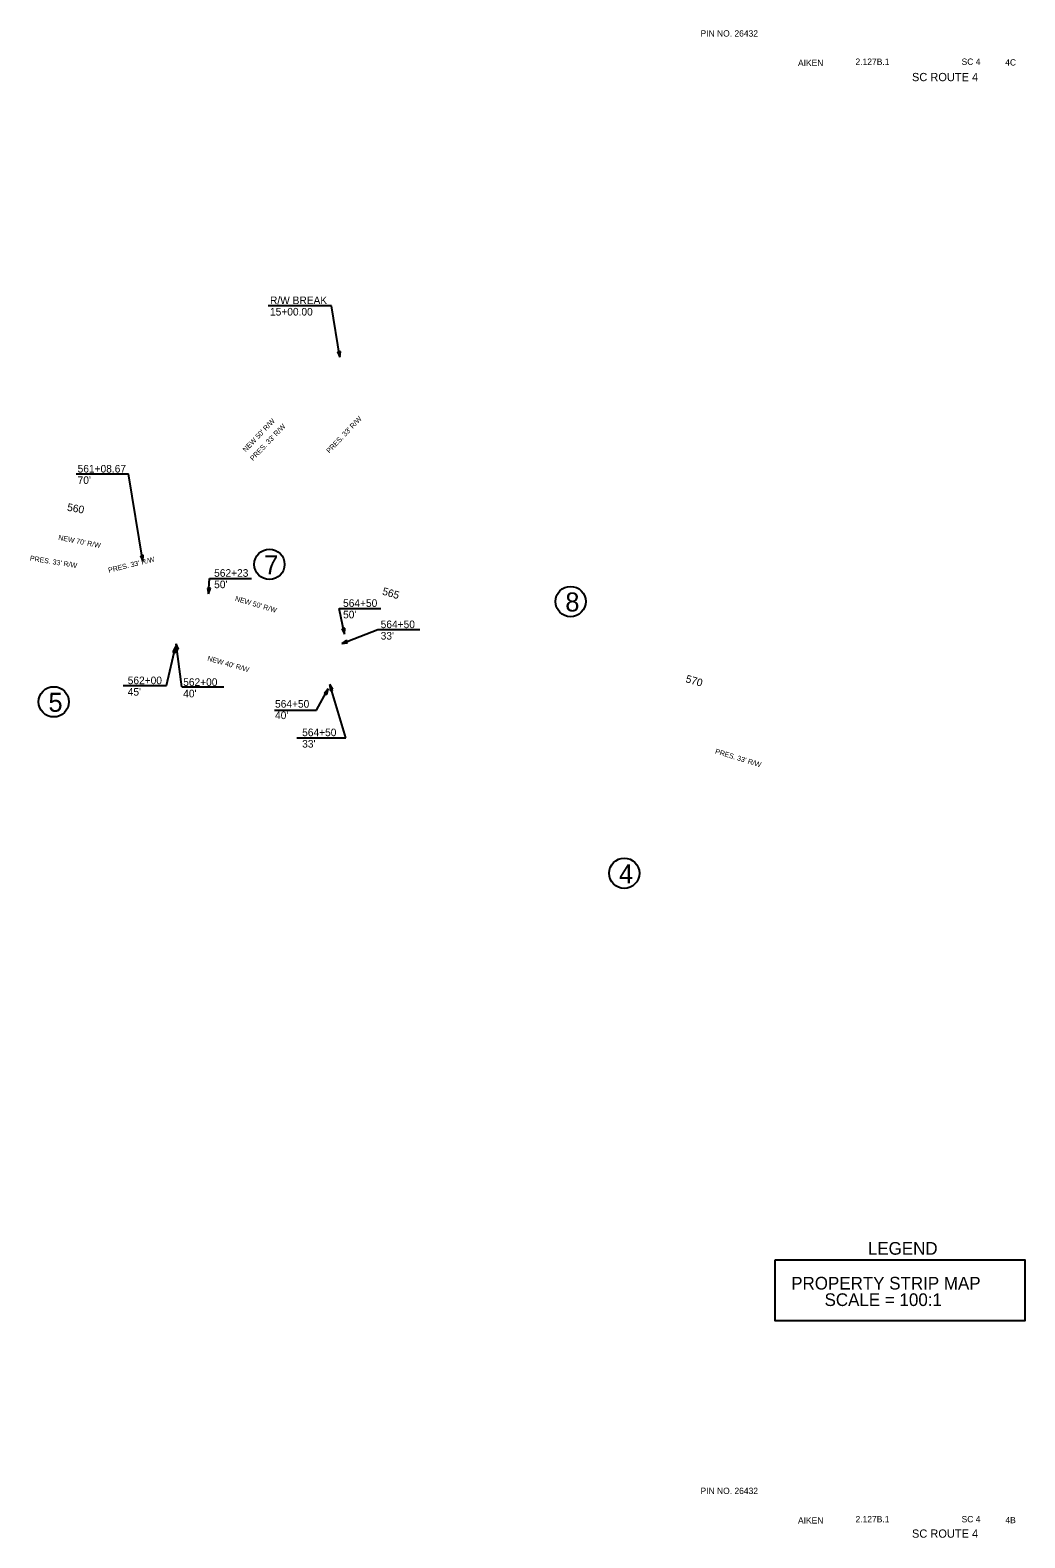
# Model space of a CAD drawing. Extents: x -64038 to -60878, y 1838 to 8465.
# Drawn here: x -62447 to -60878, y 6087 to 8465 of the extents above; entities that cross this region are included whole.
import ezdxf

# ---------------------------------------------------------------- set-up
doc = ezdxf.new("R2010")
doc.units = 0
for name, color, linetype in [('Level 1', 7, 'Continuous'), ('Level 13', 7, 'Continuous'), ('Level 21', 7, 'Continuous'), ('Level 24', 7, 'Continuous'), ('Level 25', 7, 'Continuous'), ('Level 33', 7, 'Continuous')]:
    doc.layers.add(name, color=color, linetype=linetype)

msp = doc.modelspace()

# ---------------------------------------------------------------- linework, layer by layer
at = {"layer": 'Level 1'}
msp.add_lwpolyline([(-61272.3, 6525.3), (-60878.4, 6525.3), (-60878.4, 6429), (-61272.3, 6429)], close=True, dxfattribs=at)
at = {"layer": 'Level 24'}
for p, q in [((-61957.9, 7958.1), (-61962.4, 7957.4)), ((-61962.4, 7957.4), (-61958.7, 7948.9)), ((-61958.7, 7948.9), (-61957.9, 7958.1)), ((-62268.7, 7636.6), (-62273.1, 7635.8)), ((-62273.1, 7635.8), (-62269.4, 7627.3)), ((-62269.4, 7627.3), (-62268.7, 7636.6)), ((-62162.8, 7584.6), (-62167.3, 7584.9)), ((-62167.3, 7584.9), (-62165.8, 7575.8)), ((-62165.8, 7575.8), (-62162.8, 7584.6)), ((-61951, 7521.5), (-61955.4, 7520.6)), ((-61955.4, 7520.6), (-61951.4, 7512.3)), ((-61951.4, 7512.3), (-61951, 7521.5)), ((-62218.1, 7492.2), (-62222.3, 7484)), ((-62217.9, 7482.9), (-62218.1, 7492.2)), ((-62216.7, 7497), (-62217.7, 7487.8)), ((-62213.3, 7488.4), (-62216.7, 7497)), ((-61948.2, 7502.9), (-61955.8, 7497.6)), ((-61948.2, 7502.9), (-61955.8, 7497.6)), ((-61955.8, 7497.6), (-61946.6, 7498.7)), ((-61955.8, 7497.6), (-61946.6, 7498.7)), ((-61946.6, 7498.7), (-61948.2, 7502.9)), ((-61946.6, 7498.7), (-61948.2, 7502.9)), ((-62222.3, 7484), (-62217.9, 7482.9)), ((-62217.7, 7487.8), (-62213.3, 7488.4)), ((-61977, 7426), (-61983.3, 7419.2)), ((-61983.3, 7419.2), (-61979.3, 7417)), ((-61979.3, 7417), (-61977, 7426)), ((-61974.6, 7432.6), (-61974.2, 7423.3)), ((-61969.9, 7424.6), (-61974.6, 7432.6)), ((-61974.2, 7423.3), (-61969.9, 7424.6))]:
    msp.add_line(p, q, dxfattribs=at)
at = {"layer": 'Level 25'}
for centre in [(-62069.7, 7622.2), (-61594.8, 7563.6), (-62409.9, 7405.4), (-61510.2, 7135.1)]:
    msp.add_circle(centre, 23.9, dxfattribs=at)
at = {"layer": 'Level 33'}
for p, q in [((-61972.1, 8029.7), (-62071.6, 8029.7)), ((-61958.7, 7948.9), (-61972.1, 8029.7)), ((-62374.4, 7765.1), (-62292.2, 7765.1)), ((-62269.4, 7627.3), (-62292.2, 7765.1)), ((-62165.8, 7575.8), (-62164, 7599.8)), ((-62164, 7599.8), (-62098, 7599.8)), ((-61959.8, 7552.5), (-61893.8, 7552.5)), ((-61951.4, 7512.3), (-61959.8, 7552.5)), ((-61955.8, 7497.6), (-61898.7, 7519.5)), ((-61898.7, 7519.5), (-61832.8, 7519.5)), ((-62232.3, 7431.3), (-62218.1, 7492.2)), ((-62207.7, 7429.1), (-62216.7, 7497)), ((-62300.3, 7431.3), (-62232.3, 7431.3)), ((-62207.7, 7429.1), (-62141.7, 7429.1)), ((-61995.7, 7392), (-61977, 7426)), ((-61949.1, 7348.7), (-61974.6, 7432.6)), ((-62061.6, 7392), (-61995.7, 7392)), ((-62026.3, 7348.7), (-61949.1, 7348.7))]:
    msp.add_line(p, q, dxfattribs=at)

# ---------------------------------------------------------------- texts
at = {"layer": 'Level 1'}
for s, height, p in [('PIN NO. 26432', 10, (-61389.9, 8454.5)), ('AIKEN', 10, (-61236.2, 8408)), (' 2.127B.1', 10, (-61149.2, 8409.9)), ('SC 4', 10, (-60978.2, 8409.9)), ('4C', 10, (-60909.4, 8408.8)), ('LEGEND', 20, (-61126, 6533.5)), ('PROPERTY STRIP MAP', 20, (-61246.9, 6478.6)), ('SCALE = 100:1', 20, (-61194.3, 6452.6)), ('PIN NO. 26432', 10, (-61389.9, 6156.1)), ('AIKEN', 10, (-61236.2, 6109.6)), (' 2.127B.1', 10, (-61149.2, 6111.5)), ('SC 4', 10, (-60978.2, 6111.5)), ('4B', 10, (-60909.1, 6110.1))]:
    msp.add_text(s, height=height, dxfattribs=at).set_placement(p)
at = {"layer": 'Level 13'}
for p in [(-61056.4, 8384.2), (-61056.4, 6087.2)]:
    msp.add_text('SC ROUTE 4', height=13, dxfattribs=at).set_placement(p)
at = {"layer": 'Level 21'}
for s, rotation, p in [('560', 349.8036, (-62389.4, 7706.9)), ('565', 343.4944, (-61892.7, 7574.8)), ('570', 343.4944, (-61414.3, 7436.7))]:
    msp.add_text(s, height=12, rotation=rotation, dxfattribs=at).set_placement(p)
at = {"layer": 'Level 25'}
for s, p in [('7', (-62078, 7606.4)), ('8', (-61603.1, 7547.9)), ('5', (-62418.2, 7389.7)), ('4', (-61518.5, 7119.4))]:
    msp.add_text(s, height=30, dxfattribs=at).set_placement(p)
at = {"layer": 'Level 33'}
for s, p in [('R/W BREAK', (-62068.8, 8032.6)), ('15+00.00', (-62068.8, 8014.6)), ('561+08.67', (-62372.2, 7767)), ("70'", (-62372.2, 7749)), ('562+23', (-62156.9, 7602.6)), ("50'", (-62156.9, 7584.6)), ('564+50', (-61953.6, 7555.1)), ("50'", (-61953.6, 7537.1)), ('564+50', (-61894.3, 7521.6)), ("33'", (-61894.3, 7503.6)), ('562+00', (-62293.2, 7433.2)), ('562+00', (-62205.7, 7430.5)), ("45'", (-62293.2, 7415.2)), ("40'", (-62205.7, 7412.5)), ('564+50', (-62060.9, 7396.2)), ("40'", (-62060.9, 7378.2)), ('564+50', (-62018.1, 7351.2)), ("33'", (-62018.1, 7333.2))]:
    msp.add_text(s, height=12, dxfattribs=at).set_placement(p)
for s, rotation, p in [("NEW 50' R/W", 46.3699, (-62107, 7798.6)), ("PRES. 33' R/W", 46.3699, (-61975.2, 7796.8)), ("PRES. 33' R/W", 46.3699, (-62095.5, 7784.8)), ("NEW 70' R/W", 348.7635, (-62403.2, 7661)), ("PRES. 33' R/W", 350.7318, (-62447.9, 7628.3)), ("PRES. 33' R/W", 13.7852, (-62323, 7608.9)), ("NEW 50' R/W", 343.3735, (-62124.6, 7565)), ("NEW 40' R/W", 344.0506, (-62168.2, 7470.6)), ("PRES. 33' R/W", 342.8701, (-61367.5, 7324.1))]:
    msp.add_text(s, height=8, rotation=rotation, dxfattribs=at).set_placement(p)

doc.saveas('drawing.dxf')
